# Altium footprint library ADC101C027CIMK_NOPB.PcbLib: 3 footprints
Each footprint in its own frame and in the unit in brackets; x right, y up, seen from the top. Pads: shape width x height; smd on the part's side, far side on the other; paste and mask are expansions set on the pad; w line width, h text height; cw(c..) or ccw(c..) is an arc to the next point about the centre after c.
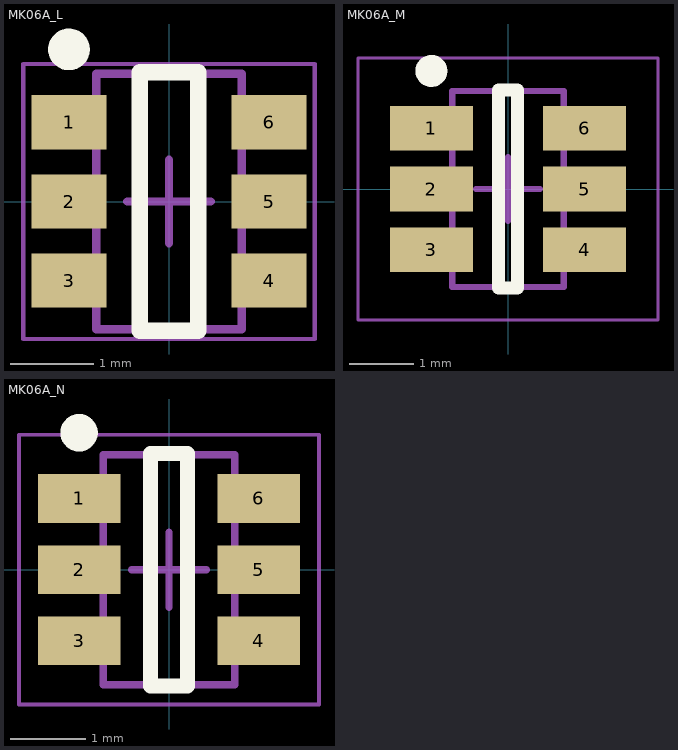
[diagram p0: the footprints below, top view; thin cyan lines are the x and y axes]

## MK06A_L [mm] "SOT23, 6-Leads, Body 3.0x1.7mm, Pitch 0.95mm, Lead Span 2.9mm, IPC High Density"
height 1
pads (6):
  rect 0.9x0.65 smd: 1(-1.2,0.95) 2(-1.2,0) 3(-1.2,-0.95) 4(1.2,-0.95) 5(1.2,0) 6(1.2,0.95)
Top Overlay:
  circle w0.25: c-1.2,1.825 r0.125
  lines w0.2: -0.35,-1.55 -0.35,1.55 0.35,1.55 0.35,-1.55 -0.35,-1.55
Mechanical 13:
  lines w0.1: -0.875,-1.535 0.875,-1.535 0.875,1.535 -0.875,1.535 -0.875,-1.535
Mechanical 15:
  lines w0.05: -1.75,-1.65 1.75,-1.65 1.75,1.65 -1.75,1.65 -1.75,-1.65
  lines w0.1: -0.5,0 0.5,0 ; 0,-0.5 0,0.5
3D body: height 1, standoff 0.01, extent -0.875,-1.535 0.875,1.535

## MK06A_M [mm] "SOT23, 6-Leads, Body 3.0x1.7mm, Pitch 0.95mm, Lead Span 2.9mm, IPC Low Density"
height 1
pads (6):
  rect 1.3x0.7 smd: 1(-1.2,0.95) 2(-1.2,0) 3(-1.2,-0.95) 4(1.2,-0.95) 5(1.2,0) 6(1.2,0.95)
Top Overlay:
  circle w0.25: c-1.2,1.85 r0.125
  lines w0.2: -0.15,-1.55 -0.15,1.55 0.15,1.55 0.15,-1.55 -0.15,-1.55
Mechanical 13:
  lines w0.1: -0.875,-1.535 0.875,-1.535 0.875,1.535 -0.875,1.535 -0.875,-1.535
Mechanical 15:
  lines w0.05: -2.35,-2.05 2.35,-2.05 2.35,2.05 -2.35,2.05 -2.35,-2.05
  lines w0.1: -0.5,0 0.5,0 ; 0,-0.5 0,0.5
3D body: height 1, standoff 0.01, extent -0.875,-1.535 0.875,1.535

## MK06A_N [mm] "SOT23, 6-Leads, Body 3.0x1.7mm, Pitch 0.95mm, Lead Span 2.9mm, IPC Medium Density"
height 1
pads (6):
  rect 1.1x0.65 smd: 1(-1.2,0.95) 2(-1.2,0) 3(-1.2,-0.95) 4(1.2,-0.95) 5(1.2,0) 6(1.2,0.95)
Top Overlay:
  circle w0.25: c-1.2,1.825 r0.125
  lines w0.2: -0.25,-1.55 -0.25,1.55 0.25,1.55 0.25,-1.55 -0.25,-1.55
Mechanical 13:
  lines w0.1: -0.875,-1.535 0.875,-1.535 0.875,1.535 -0.875,1.535 -0.875,-1.535
Mechanical 15:
  lines w0.05: -2,-1.8 2,-1.8 2,1.8 -2,1.8 -2,-1.8
  lines w0.1: -0.5,0 0.5,0 ; 0,-0.5 0,0.5
3D body: height 1, standoff 0.01, extent -0.875,-1.535 0.875,1.535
